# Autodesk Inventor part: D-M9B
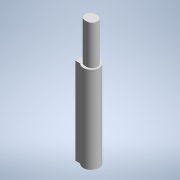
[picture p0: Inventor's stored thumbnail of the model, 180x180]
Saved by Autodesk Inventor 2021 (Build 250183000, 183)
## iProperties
Category: PARTsolutions
Company: SMC
Part Number: D-M9B
Material: Genérico
Catalog Web Link: www.cadenas.de
Description: MSQX SW-Low-Speed Rotary Table Rack & Pinion Style
Vendor: SMC
Document SubType Name: Modeling
Designer: partserver
Manufacturer: SMC
Mass: 0.394414 g
Surface Area: 4.48271 cm^2
Volume: 0.394414 cm^3
Density: 1 g/cm^3
Appearance: PSOLRGB-255-255-255
PSOL_IDENT_0: {$CADENAS_DATA\23d-libs\smc_jp\actuator\rotary_actuator\msqx\parts\msqx_sw.prj},163 {VTYP=3D},{NB=D-
PSOL_IDENT_1: M9B_MSQX},{LINA=D-M9B},{NN=MSQX SW},{DATE=09.12.2020 02:49:36},{GEOMDATE=19.01.2011 00:00:00},{VERSI
PSOL_IDENT_2: ON=},{LINEID=110},{WBVAR=AUTOSW},{WBNUMERIC=}  {NB=D-M9B_MSQX},{LINA=D-M9B},{KT=DUMMY},{AUTOSW=-M9B}
NB: D-M9B_MSQX
NN: MSQX SW
NT: Low-Speed Rotary Table Rack & Pinion Style
NBSYN: D$AUTOSW._MSQX
LINA: D-M9B
CATALOG: SMC (JP
AUTOSW: M9B Solid state-General-Grommet-Indicator light:Yes-2 wire-In line
SUPPLIER: SMC
ARTICLENO: D-M9B_MSQX
BOMINFO: D-M9B
CREATOR: CADENAS GmbH
Title: D-M9B
Author: Cadenas PARTsolutions
Comments: Low-Speed Rotary Table Rack & Pinion Style
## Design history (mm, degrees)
sketch "Sketch_1"
  geometry: L1 (1.428, -1.4)-(2.6, -1.4); L2 (2.6, -1.4)-(2.6, 1.4); L3 (2.6, 1.4)-(1.428, 1.4); A1 r 2 centre (0, 0) between (1.428, 1.4) and (1.428, -1.4)
  constraints: 6 end point, 2 point on circle, 1 centre point
  dimensions: "d11" = 2 radius of A1; "d12" = 2.8 distance of L1.end L2.end; "d14" = 2.6 distance from line of L2 A1.centre
extrude "Extrusion1" join sketch "Sketch_1" distance "d0" = 22; taper "d1" = 0 deg
sketch "Sketch_2"
  geometry: L1 (-0.25, -1.35)-(0.25, -1.35); L2 (0.25, 1.35)-(-0.25, 1.35); A1 r 1.35 centre (-0.25, 0) between (-0.25, 1.35) and (-0.25, -1.35); A2 r 1.35 centre (0.25, 0) between (0.25, -1.35) and (0.25, 1.35)
  constraints: 4 end point, 4 point on circle, 2 centre point
extrude "Extrusion2" join sketch "Sketch_2" distance "d2" = 10; taper "d3" = 0 deg
sketch "Sketch_8"
  geometry: C1 r 1.25 at (2, 0); C2 r 1.05 at (2, 0); 2 further points
  constraints: 2 centre point
extrude "Extrusion3" cut sketch "Sketch_8" distance "d4" = 0.1; taper "d5" = 0 deg
sketch "Sketch_9"
  geometry: L1 (7, 0.4)-(7, -0.4); L2 (7.4, -0.8)-(9.6, -0.8); L3 (10, -0.4)-(10, 0.4); L4 (9.6, 0.8)-(7.4, 0.8); A1 r 0.4 centre (7.4, -0.4) between (7, -0.4) and (7.4, -0.8); A2 r 0.4 centre (9.6, -0.4) between (9.6, -0.8) and (10, -0.4); A3 r 0.4 centre (9.6, 0.4) between (10, 0.4) and (9.6, 0.8); A4 r 0.4 centre (7.4, 0.4) between (7.4, 0.8) and (7, 0.4)
  constraints: 8 end point, 8 point on circle, 4 centre point
extrude "Extrusion4" cut sketch "Sketch_9" distance "d6" = 0.1; taper "d7" = 0 deg
sketch "Sketch_10"
  geometry: L1 (0.966, 0.609)-(2.609, -1.034); L2 (3.034, -0.609)-(1.391, 1.034); A1 r 1.2 centre (2, 0) between (2.609, -1.034) and (3.034, -0.609); A2 r 1.2 centre (2, 0) between (1.391, 1.034) and (0.966, 0.609)
  constraints: 4 end point, 4 point on circle, 2 centre point
extrude "Extrusion5" cut sketch "Sketch_10" distance "d8" = 0.1; taper "d9" = 0 deg
node "sw_set_XY"
node "sw_set_YZ"
node "sw_set_ZX"
node "sw_set_X"
node "sw_set_Y"
node "sw_set_Z"
node "sw_set_Center"
body "Solid1"
other parameters: "d10" = 0
